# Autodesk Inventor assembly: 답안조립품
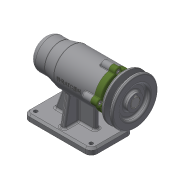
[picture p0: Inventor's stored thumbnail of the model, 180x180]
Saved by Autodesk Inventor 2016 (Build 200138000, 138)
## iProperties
Created: 2019-07
Part Number: 답안조립품
Material: 일반
Document SubType Name: Assembly
Designer: 3sil_cad0123
Author: 3sil_cad0123
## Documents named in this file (12)
- C:\Users\3sil_cad0123\Desktop\490704V1001\답안조립품.iam
- C:\Users\3sil_cad0123\Desktop\490704V1001\본체.ipt
- C:\Users\3sil_cad0123\Desktop\490704V1001\축.ipt
- C:\Users\3sil_cad0123\Desktop\490704V1001\커버.ipt
- C:\Users\3sil_cad0123\Desktop\490704V1001\키 5 x 5 x 16.ipt
- C:\Users\3sil_cad0123\Desktop\490704V1001\멈춤나사 M3.ipt
- C:\Users\3sil_cad0123\Desktop\490704V1001\베어링 6004.ipt
- C:\Users\3sil_cad0123\Desktop\490704V1001\베어링 51202.ipt
- C:\Users\3sil_cad0123\Desktop\490704V1001\볼트 M4.ipt
- C:\Users\3sil_cad0123\Desktop\490704V1001\어댑터슬리브.ipt
- C:\Users\3sil_cad0123\Desktop\490704V1001\오일 실.ipt
- C:\Users\3sil_cad0123\Desktop\490704V1001\V벨트풀리.ipt
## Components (1 placed, 1 different names)
1. V벨트풀리:1
